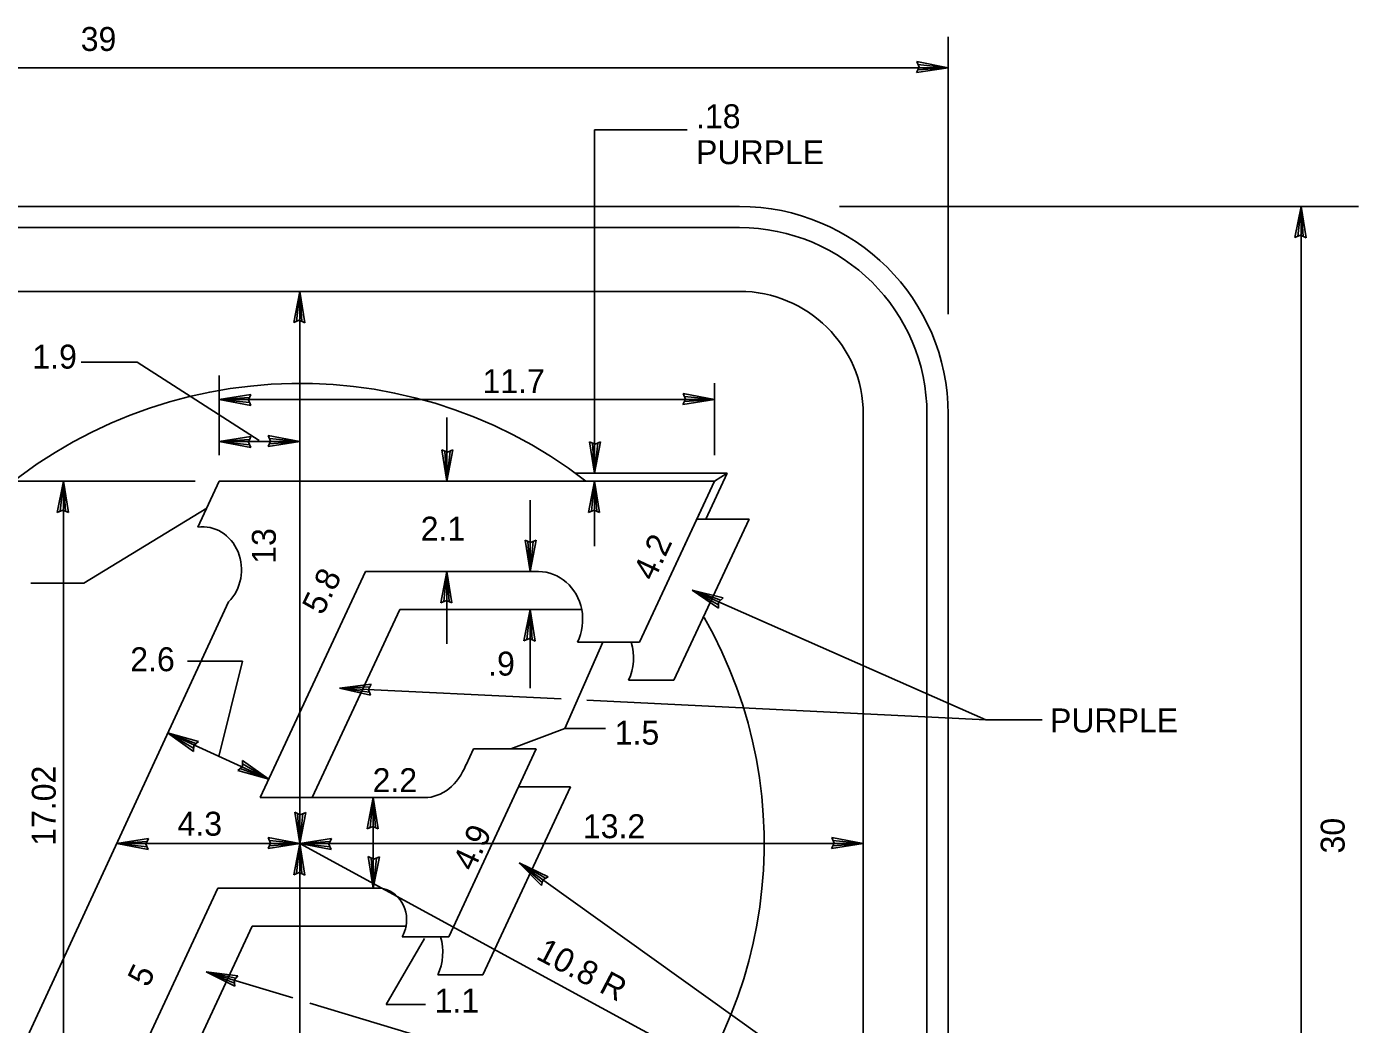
# Model space of a CAD drawing. Extents: x 10268197 to 10269179, y 2141503 to 2142677.
# Drawn here: x 10268695.42 to 10268734.62, y 2142011.21 to 2142040.57 of the extents above; entities that cross this region are included whole.
import ezdxf

# ---------------------------------------------------------------- set-up
doc = ezdxf.new("R2010")
doc.units = 0
for name, color, linetype in [('1', 7, 'Continuous'), ('Default', 7, 'Continuous'), ('TextMisc', 7, 'Continuous'), ('TextShtNo', 7, 'Continuous')]:
    doc.layers.add(name, color=color, linetype=linetype)

msp = doc.modelspace()

# ---------------------------------------------------------------- linework, layer by layer
at = {"layer": '1'}
for p, q in [((10268697.022, 2142030.7), (10268698.674, 2142030.7)), ((10268698.674, 2142030.7), (10268702.262, 2142028.387)), ((10268697.098, 2142024.19), (10268700.724, 2142026.401)), ((10268695.536, 2142024.19), (10268697.098, 2142024.19)), ((10268715.007, 2142023.983), (10268723.658, 2142020.169)), ((10268700.151, 2142021.903), (10268701.774, 2142021.903)), ((10268701.075, 2142019.096), (10268701.774, 2142021.903)), ((10268704.624, 2142021.106), (10268711.156, 2142020.785)), ((10268711.908, 2142020.748), (10268723.658, 2142020.169)), ((10268723.658, 2142020.169), (10268725.31, 2142020.169)), ((10268709.921, 2142015.962), (10268724.389, 2142005.619)), ((10268700.704, 2142012.756), (10268703.254, 2142011.988)), ((10268703.757, 2142011.836), (10268724.389, 2142005.619))]:
    msp.add_line(p, q, dxfattribs=at)
at = {"layer": 'Default'}
for p, q in [((10268722.546, 2142032.108), (10268722.546, 2142040.27)), ((10268722.546, 2142039.361), (10268721.619, 2142039.539)), ((10268721.619, 2142039.539), (10268721.687, 2142039.376)), ((10268673.796, 2142039.361), (10268722.546, 2142039.361)), ((10268721.687, 2142039.376), (10268721.613, 2142039.215)), ((10268722.546, 2142039.361), (10268721.613, 2142039.215)), ((10268722.546, 2142039.361), (10268721.653, 2142039.299)), ((10268722.546, 2142039.361), (10268721.654, 2142039.453)), ((10268712.135, 2142037.534), (10268714.857, 2142037.534)), ((10268712.135, 2142027.43), (10268712.135, 2142037.534)), ((10268719.344, 2142035.28), (10268734.621, 2142035.28)), ((10268732.934, 2142035.28), (10268732.755, 2142034.362)), ((10268732.934, 2142035.28), (10268732.841, 2142034.397)), ((10268732.934, 2142035.28), (10268732.934, 2141997.78)), ((10268732.934, 2142035.28), (10268733.081, 2142034.356)), ((10268732.934, 2142035.28), (10268732.997, 2142034.396)), ((10268732.755, 2142034.362), (10268732.92, 2142034.429)), ((10268732.92, 2142034.429), (10268733.081, 2142034.356)), ((10268679.942, 2142032.78), (10268716.4, 2142032.78)), ((10268703.457, 2142032.78), (10268703.278, 2142031.861)), ((10268703.457, 2142032.78), (10268703.364, 2142031.897)), ((10268703.457, 2142016.53), (10268703.457, 2142032.78)), ((10268703.457, 2142032.78), (10268703.605, 2142031.856)), ((10268703.457, 2142032.78), (10268703.52, 2142031.895)), ((10268703.278, 2142031.861), (10268703.443, 2142031.929)), ((10268703.443, 2142031.929), (10268703.605, 2142031.856)), ((10268701.087, 2142027.958), (10268701.087, 2142030.306)), ((10268715.67, 2142027.958), (10268715.67, 2142030.081)), ((10268701.087, 2142029.598), (10268702.02, 2142029.744)), ((10268701.945, 2142029.583), (10268702.02, 2142029.744)), ((10268715.67, 2142029.598), (10268714.744, 2142029.776)), ((10268714.744, 2142029.776), (10268714.812, 2142029.612)), ((10268715.67, 2142029.598), (10268714.779, 2142029.69)), ((10268701.087, 2142029.598), (10268701.981, 2142029.66)), ((10268701.087, 2142029.598), (10268702.014, 2142029.42)), ((10268701.087, 2142029.598), (10268701.979, 2142029.506)), ((10268701.087, 2142029.598), (10268703.457, 2142029.598)), ((10268702.014, 2142029.42), (10268701.945, 2142029.583)), ((10268703.457, 2142029.598), (10268715.67, 2142029.598)), ((10268714.812, 2142029.612), (10268714.738, 2142029.451)), ((10268715.67, 2142029.598), (10268714.738, 2142029.451)), ((10268715.67, 2142029.598), (10268714.777, 2142029.535)), ((10268707.788, 2142027.195), (10268707.788, 2142029.064)), ((10268720.046, 2142003.891), (10268720.046, 2142029.168)), ((10268703.457, 2142028.359), (10268702.53, 2142028.537)), ((10268702.53, 2142028.537), (10268702.599, 2142028.374)), ((10268701.087, 2142028.359), (10268702.02, 2142028.505)), ((10268701.087, 2142028.359), (10268701.981, 2142028.421)), ((10268701.087, 2142028.359), (10268703.457, 2142028.359)), ((10268701.087, 2142028.359), (10268702.014, 2142028.181)), ((10268701.087, 2142028.359), (10268701.979, 2142028.267)), ((10268701.945, 2142028.344), (10268702.02, 2142028.505)), ((10268702.014, 2142028.181), (10268701.945, 2142028.344)), ((10268702.599, 2142028.374), (10268702.525, 2142028.212)), ((10268703.457, 2142028.359), (10268702.525, 2142028.212)), ((10268703.457, 2142028.359), (10268702.564, 2142028.297)), ((10268703.457, 2142028.359), (10268702.565, 2142028.451)), ((10268707.788, 2142027.195), (10268707.64, 2142028.119)), ((10268707.802, 2142028.045), (10268707.64, 2142028.119)), ((10268712.135, 2142027.43), (10268711.987, 2142028.353)), ((10268712.15, 2142028.28), (10268711.987, 2142028.353)), ((10268712.135, 2142027.43), (10268712.072, 2142028.315)), ((10268712.135, 2142027.43), (10268712.315, 2142028.348)), ((10268712.135, 2142027.43), (10268712.228, 2142028.312)), ((10268712.315, 2142028.348), (10268712.15, 2142028.28)), ((10268707.788, 2142027.195), (10268707.725, 2142028.08)), ((10268707.788, 2142027.195), (10268707.967, 2142028.113)), ((10268707.788, 2142027.195), (10268707.88, 2142028.079)), ((10268707.967, 2142028.113), (10268707.802, 2142028.045)), ((10268711.881, 2142027.195), (10268711.569, 2142027.43)), ((10268711.569, 2142027.43), (10268716.041, 2142027.43)), ((10268711.569, 2142027.43), (10268716.041, 2142027.43)), ((10268716.041, 2142027.43), (10268711.569, 2142027.43)), ((10268711.569, 2142027.43), (10268716.041, 2142027.43)), ((10268716.041, 2142027.43), (10268715.409, 2142026.074)), ((10268716.041, 2142027.43), (10268715.409, 2142026.074)), ((10268715.67, 2142027.195), (10268716.041, 2142027.43)), ((10268715.67, 2142027.195), (10268716.041, 2142027.43)), ((10268683.847, 2142027.195), (10268700.38, 2142027.195)), ((10268694.99, 2142027.195), (10268699.515, 2142027.195)), ((10268696.498, 2142027.195), (10268696.319, 2142026.277)), ((10268696.498, 2142027.195), (10268696.405, 2142026.312)), ((10268696.498, 2142005.913), (10268696.498, 2142027.195)), ((10268696.498, 2142027.195), (10268696.646, 2142026.271)), ((10268696.498, 2142027.195), (10268696.561, 2142026.311)), ((10268701.087, 2142027.195), (10268700.456, 2142025.841)), ((10268715.67, 2142027.195), (10268701.087, 2142027.195)), ((10268715.67, 2142027.195), (10268701.087, 2142027.195)), ((10268715.67, 2142027.195), (10268711.881, 2142027.195)), ((10268712.135, 2142027.195), (10268711.955, 2142026.277)), ((10268712.135, 2142027.195), (10268712.042, 2142026.312)), ((10268712.135, 2142025.283), (10268712.135, 2142027.195)), ((10268712.135, 2142027.195), (10268712.283, 2142026.271)), ((10268712.135, 2142027.195), (10268712.198, 2142026.311)), ((10268715.67, 2142027.195), (10268713.459, 2142022.455)), ((10268715.149, 2142026.074), (10268715.67, 2142027.195)), ((10268710.236, 2142024.536), (10268710.236, 2142026.637)), ((10268696.319, 2142026.277), (10268696.484, 2142026.345)), ((10268696.484, 2142026.345), (10268696.646, 2142026.271)), ((10268711.955, 2142026.277), (10268712.121, 2142026.345)), ((10268712.121, 2142026.345), (10268712.283, 2142026.271)), ((10268716.682, 2142026.074), (10268714.471, 2142021.335)), ((10268715.409, 2142026.074), (10268715.149, 2142026.074)), ((10268715.149, 2142026.074), (10268716.682, 2142026.074)), ((10268710.236, 2142024.536), (10268710.089, 2142025.46)), ((10268710.251, 2142025.386), (10268710.089, 2142025.46)), ((10268710.236, 2142024.536), (10268710.173, 2142025.42)), ((10268710.236, 2142024.536), (10268710.416, 2142025.454)), ((10268710.236, 2142024.536), (10268710.33, 2142025.419)), ((10268710.416, 2142025.454), (10268710.251, 2142025.386)), ((10268702.289, 2142017.884), (10268705.39, 2142024.536)), ((10268702.289, 2142017.884), (10268705.39, 2142024.536)), ((10268705.39, 2142024.536), (10268710.488, 2142024.536)), ((10268706.348, 2142024.536), (10268705.39, 2142024.536)), ((10268705.39, 2142024.536), (10268710.488, 2142024.536)), ((10268705.39, 2142024.536), (10268710.488, 2142024.536)), ((10268710.488, 2142024.536), (10268706.348, 2142024.536)), ((10268707.788, 2142024.536), (10268707.608, 2142023.618)), ((10268707.788, 2142024.536), (10268707.694, 2142023.652)), ((10268707.788, 2142022.404), (10268707.788, 2142024.536)), ((10268707.788, 2142024.536), (10268707.935, 2142023.613)), ((10268707.788, 2142024.536), (10268707.851, 2142023.651)), ((10268715.007, 2142023.983), (10268715.92, 2142023.757)), ((10268715.007, 2142023.983), (10268715.787, 2142023.461)), ((10268715.007, 2142023.983), (10268715.788, 2142023.553)), ((10268715.007, 2142023.983), (10268715.851, 2142023.695)), ((10268694.844, 2142009.556), (10268701.361, 2142023.642)), ((10268706.402, 2142023.414), (10268703.823, 2142017.884)), ((10268706.402, 2142023.414), (10268703.823, 2142017.884)), ((10268711.757, 2142023.414), (10268706.402, 2142023.414)), ((10268711.757, 2142023.414), (10268706.402, 2142023.414)), ((10268707.608, 2142023.618), (10268707.773, 2142023.686)), ((10268707.773, 2142023.686), (10268707.935, 2142023.613)), ((10268710.236, 2142023.414), (10268710.057, 2142022.496)), ((10268710.236, 2142023.414), (10268710.143, 2142022.532)), ((10268710.236, 2142021.106), (10268710.236, 2142023.414)), ((10268710.236, 2142023.414), (10268710.384, 2142022.491)), ((10268710.236, 2142023.414), (10268710.3, 2142022.53)), ((10268715.787, 2142023.461), (10268715.789, 2142023.638)), ((10268715.789, 2142023.638), (10268715.92, 2142023.757)), ((10268710.057, 2142022.496), (10268710.222, 2142022.564)), ((10268710.222, 2142022.564), (10268710.384, 2142022.491)), ((10268711.262, 2142019.92), (10268712.375, 2142022.455)), ((10268713.459, 2142022.455), (10268711.636, 2142022.455)), ((10268704.624, 2142021.106), (10268705.557, 2142021.223)), ((10268704.624, 2142021.106), (10268705.515, 2142021.14)), ((10268704.624, 2142021.106), (10268705.539, 2142020.898)), ((10268704.624, 2142021.106), (10268705.508, 2142020.985)), ((10268705.477, 2142021.064), (10268705.557, 2142021.223)), ((10268705.539, 2142020.898), (10268705.477, 2142021.064)), ((10268713.136, 2142021.335), (10268714.471, 2142021.335)), ((10268711.262, 2142019.92), (10268709.673, 2142019.32)), ((10268711.262, 2142019.92), (10268712.457, 2142019.92)), ((10268702.542, 2142018.426), (10268699.563, 2142019.788)), ((10268699.563, 2142019.788), (10268700.472, 2142019.534)), ((10268699.563, 2142019.788), (10268700.33, 2142019.241)), ((10268699.563, 2142019.788), (10268700.333, 2142019.334)), ((10268699.563, 2142019.788), (10268700.4, 2142019.473)), ((10268700.337, 2142019.418), (10268700.472, 2142019.534)), ((10268700.33, 2142019.241), (10268700.337, 2142019.418)), ((10268710.419, 2142019.32), (10268707.841, 2142013.787)), ((10268708.569, 2142019.32), (10268708.351, 2142018.85)), ((10268708.569, 2142019.32), (10268710.419, 2142019.32)), ((10268701.768, 2142018.796), (10268701.633, 2142018.68)), ((10268702.542, 2142018.426), (10268701.705, 2142018.741)), ((10268701.775, 2142018.973), (10268701.768, 2142018.796)), ((10268702.542, 2142018.426), (10268701.772, 2142018.88)), ((10268702.542, 2142018.426), (10268701.775, 2142018.973)), ((10268702.542, 2142018.426), (10268701.633, 2142018.68)), ((10268711.43, 2142018.2), (10268708.851, 2142012.668)), ((10268709.898, 2142018.2), (10268711.43, 2142018.2)), ((10268702.289, 2142017.884), (10268707.13, 2142017.884)), ((10268707.13, 2142017.884), (10268702.289, 2142017.884)), ((10268703.247, 2142017.884), (10268704.78, 2142017.884)), ((10268705.622, 2142017.884), (10268705.443, 2142016.966)), ((10268705.622, 2142017.884), (10268705.53, 2142017.001)), ((10268705.622, 2142015.222), (10268705.622, 2142017.884)), ((10268705.622, 2142017.884), (10268705.77, 2142016.96)), ((10268705.622, 2142017.884), (10268705.685, 2142016.999)), ((10268703.457, 2142016.53), (10268703.31, 2142017.453)), ((10268703.471, 2142017.38), (10268703.31, 2142017.453)), ((10268703.457, 2142016.53), (10268703.394, 2142017.415)), ((10268703.457, 2142016.53), (10268703.637, 2142017.448)), ((10268703.457, 2142016.53), (10268703.55, 2142017.413)), ((10268703.637, 2142017.448), (10268703.471, 2142017.38)), ((10268705.443, 2142016.966), (10268705.608, 2142017.033)), ((10268705.608, 2142017.033), (10268705.77, 2142016.96)), ((10268698.07, 2142016.53), (10268699.003, 2142016.676)), ((10268698.07, 2142016.53), (10268698.963, 2142016.592)), ((10268698.07, 2142016.53), (10268703.457, 2142016.53)), ((10268698.07, 2142016.53), (10268698.997, 2142016.352)), ((10268698.07, 2142016.53), (10268698.961, 2142016.438)), ((10268698.929, 2142016.516), (10268699.003, 2142016.676)), ((10268698.997, 2142016.352), (10268698.929, 2142016.516)), ((10268702.599, 2142016.544), (10268702.525, 2142016.384)), ((10268703.457, 2142016.53), (10268702.525, 2142016.384)), ((10268703.457, 2142016.53), (10268702.53, 2142016.708)), ((10268702.53, 2142016.708), (10268702.599, 2142016.544)), ((10268703.457, 2142016.53), (10268702.564, 2142016.468)), ((10268703.457, 2142016.53), (10268702.565, 2142016.622)), ((10268703.457, 2142016.53), (10268703.278, 2142015.611)), ((10268703.457, 2142016.53), (10268703.364, 2142015.647)), ((10268703.457, 2142016.53), (10268704.39, 2142016.676)), ((10268703.457, 2142016.53), (10268704.35, 2142016.592)), ((10268703.457, 2142016.53), (10268720.046, 2142016.53)), ((10268703.457, 2142016.53), (10268704.385, 2142016.352)), ((10268703.457, 2142016.53), (10268704.349, 2142016.438)), ((10268703.457, 2141998.311), (10268703.457, 2142016.53)), ((10268703.457, 2142016.53), (10268703.605, 2142015.606)), ((10268703.457, 2142016.53), (10268703.52, 2142015.645)), ((10268703.457, 2142016.53), (10268715.441, 2142010.012)), ((10268704.316, 2142016.516), (10268704.39, 2142016.676)), ((10268704.385, 2142016.352), (10268704.316, 2142016.516)), ((10268719.187, 2142016.544), (10268719.113, 2142016.384)), ((10268720.046, 2142016.53), (10268719.113, 2142016.384)), ((10268720.046, 2142016.53), (10268719.119, 2142016.708)), ((10268719.119, 2142016.708), (10268719.187, 2142016.544)), ((10268720.046, 2142016.53), (10268719.153, 2142016.468)), ((10268720.046, 2142016.53), (10268719.154, 2142016.622)), ((10268705.622, 2142015.222), (10268705.475, 2142016.146)), ((10268705.637, 2142016.073), (10268705.475, 2142016.146)), ((10268705.622, 2142015.222), (10268705.559, 2142016.107)), ((10268705.622, 2142015.222), (10268705.802, 2142016.141)), ((10268705.622, 2142015.222), (10268705.716, 2142016.106)), ((10268705.802, 2142016.141), (10268705.637, 2142016.073)), ((10268709.921, 2142015.962), (10268710.769, 2142015.556)), ((10268709.921, 2142015.962), (10268710.578, 2142015.293)), ((10268709.921, 2142015.962), (10268710.598, 2142015.383)), ((10268709.921, 2142015.962), (10268710.688, 2142015.509)), ((10268703.278, 2142015.611), (10268703.443, 2142015.679)), ((10268703.443, 2142015.679), (10268703.605, 2142015.606)), ((10268698.359, 2142009.459), (10268701.048, 2142015.222)), ((10268701.048, 2142015.222), (10268705.748, 2142015.222)), ((10268710.578, 2142015.293), (10268710.616, 2142015.466)), ((10268710.616, 2142015.466), (10268710.769, 2142015.556)), ((10268702.061, 2142014.103), (10268699.894, 2142009.459)), ((10268706.585, 2142014.103), (10268702.061, 2142014.103)), ((10268705.998, 2142011.794), (10268707.133, 2142013.741)), ((10268706.469, 2142013.787), (10268707.841, 2142013.787)), ((10268700.704, 2142012.756), (10268701.638, 2142012.643)), ((10268700.704, 2142012.756), (10268701.542, 2142012.332)), ((10268700.704, 2142012.756), (10268701.532, 2142012.425)), ((10268700.704, 2142012.756), (10268701.577, 2142012.573)), ((10268701.522, 2142012.509), (10268701.638, 2142012.643)), ((10268701.542, 2142012.332), (10268701.522, 2142012.509)), ((10268708.851, 2142012.668), (10268707.519, 2142012.668)), ((10268705.998, 2142011.794), (10268707.161, 2142011.794))]:
    msp.add_line(p, q, dxfattribs=at)
for centre, major_axis, ratio, start_param, end_param in [((10268716.399, 2142029.168), (-3.646, 0), 0.990479, 3.141593, 4.712389), ((10268703.457, 2142016.529), (13.672, 0), 0.990479, 0.906904, 3.809231), ((10268700.609, 2142024.588), (0, 1.263), 0.898224, 3.865417, 6.41824), ((10268710.487, 2142023.116), (0, 1.419), 0.915383, 4.924065, 6.283185), ((10268710.487, 2142023.116), (0, 1.419), 0.915383, 4.924772, 6.283185), ((10268710.487, 2142023.116), (0, 1.419), 0.915383, 4.924772, 6.283185), ((10268710.487, 2142023.116), (0, 1.419), 0.915383, 4.228038, 4.924065), ((10268703.457, 2142016.529), (13.672, 0), 0.990479, 4.190341, 6.796736), ((10268711.987, 2142021.996), (0, 1.419), 0.915383, 4.227342, 5.041732), ((10268707.13, 2142019.657), (0, 1.774), 0.772325, 3.141593, 4.241405), ((10268705.748, 2142014.29), (0, 0.933), 0.915383, 4.510784, 6.283185), ((10268705.748, 2142014.29), (0, 0.933), 0.915383, 4.144801, 4.510784), ((10268706.369, 2142013.329), (0, 1.419), 0.915383, 4.227342, 5.041732)]:
    msp.add_ellipse(centre, major_axis=major_axis, ratio=ratio, start_param=start_param, end_param=end_param, dxfattribs=at)
at = {"layer": 'TextMisc'}
for p, q in [((10268679.942, 2142035.28), (10268716.4, 2142035.28)), ((10268679.942, 2142034.655), (10268716.4, 2142034.655)), ((10268721.921, 2142003.891), (10268721.921, 2142029.168)), ((10268722.546, 2142003.891), (10268722.546, 2142029.168))]:
    msp.add_line(p, q, dxfattribs=at)
for major_axis, ratio in [((-6.146, 0), 0.994352), ((-5.521, 0), 0.993713)]:
    msp.add_ellipse((10268716.399, 2142029.168), major_axis=major_axis, ratio=ratio, start_param=3.141593, end_param=4.712389, dxfattribs=at)
at = {"layer": 'TextShtNo'}
for p, q in [((10268713.459, 2142022.455), (10268715.149, 2142026.074)), ((10268716.682, 2142026.074), (10268714.471, 2142021.335)), ((10268715.149, 2142026.074), (10268716.682, 2142026.074)), ((10268702.289, 2142017.884), (10268705.39, 2142024.536)), ((10268705.39, 2142024.536), (10268710.488, 2142024.536)), ((10268706.402, 2142023.414), (10268703.823, 2142017.884)), ((10268706.402, 2142023.414), (10268711.757, 2142023.414)), ((10268711.757, 2142023.414), (10268707.36, 2142023.414)), ((10268713.217, 2142022.455), (10268713.459, 2142022.455)), ((10268714.471, 2142021.335), (10268713.136, 2142021.335)), ((10268707.841, 2142013.787), (10268709.898, 2142018.2)), ((10268711.43, 2142018.2), (10268708.851, 2142012.668)), ((10268709.898, 2142018.2), (10268711.43, 2142018.2)), ((10268703.823, 2142017.884), (10268702.289, 2142017.884)), ((10268698.359, 2142009.459), (10268701.048, 2142015.222)), ((10268701.048, 2142015.222), (10268705.748, 2142015.222)), ((10268702.061, 2142014.103), (10268699.894, 2142009.459)), ((10268706.585, 2142014.103), (10268702.061, 2142014.103)), ((10268707.598, 2142013.787), (10268707.841, 2142013.787)), ((10268708.851, 2142012.668), (10268707.519, 2142012.668))]:
    msp.add_line(p, q, dxfattribs=at)
for centre, major_axis, start_param, end_param in [((10268710.487, 2142023.116), (0, 1.419), 4.924772, 6.283185), ((10268711.987, 2142021.996), (0, 1.419), 4.227342, 5.041732), ((10268705.748, 2142014.29), (0, 0.933), 4.510784, 6.283185), ((10268706.369, 2142013.329), (0, 1.419), 4.227342, 5.041732)]:
    msp.add_ellipse(centre, major_axis=major_axis, ratio=0.915383, start_param=start_param, end_param=end_param, dxfattribs=at)

# ---------------------------------------------------------------- texts
at = {"layer": '1'}
for s, p in [('39', (10268697.01, 2142039.853)), ('.18', (10268715.123, 2142037.579)), ('PURPLE', (10268715.123, 2142036.522)), ('1.9', (10268695.586, 2142030.506)), ('11.7', (10268708.837, 2142029.785)), ('2.1', (10268707.018, 2142025.445)), ('2.6', (10268698.468, 2142021.602)), ('.9', (10268709.003, 2142021.473)), ('PURPLE', (10268725.544, 2142019.801)), ('1.5', (10268712.73, 2142019.442)), ('2.2', (10268705.602, 2142018.044)), ('4.3', (10268699.859, 2142016.763)), ('13.2', (10268711.793, 2142016.689)), ('1.1', (10268707.427, 2142011.557))]:
    msp.add_text(s, height=0.7047, dxfattribs=at).set_placement(p)
for s, height, rotation, p in [('13', 0.7047, 90, (10268702.752, 2142024.763)), ('4.2', 0.7047, 64.85, (10268713.882, 2142024.225)), ('5.8', 0.7047, 63.808, (10268704.127, 2142023.223)), ('17.02', 0.7047, 90, (10268696.273, 2142016.465)), ('30', 0.7047, 90, (10268734.217, 2142016.24)), ('4.9', 0.7047, 64.85, (10268708.567, 2142015.682)), ('10.8 R', 0.7047, 332.3505, (10268710.378, 2142013.156)), ('5', 0.705, 63.808, (10268698.988, 2142012.273))]:
    msp.add_text(s, height=height, rotation=rotation, dxfattribs=at).set_placement(p)

doc.saveas('drawing.dxf')
